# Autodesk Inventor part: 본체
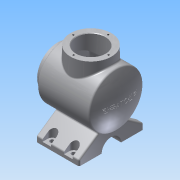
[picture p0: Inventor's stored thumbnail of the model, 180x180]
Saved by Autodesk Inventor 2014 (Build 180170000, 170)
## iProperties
Created: 2017-04
Part Number: 본체
Material: 알루미늄 6061
Document SubType Name: Modeling
Designer: SCD-A12
Density: 2.71 g/cm^3
Appearance: 알루미늄 - 평지
Mass: 1792.45 g
Surface Area: 1064.52 cm^2
Volume: 661.422 cm^3
Author: SCD-A12
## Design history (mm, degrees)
sketch "스케치1"
  geometry: L1 (12, 50)-(108.336, 50); L2 (0, 0)-(120, 0); L3 (0, 38)-(12, 38); L4 (12, 38)-(12, 50); L5 (0, 38)-(0, 0); L6 (0, 0)-(0, 27); L7 (0, 27)-(22, 27); L8 (22, 27)-(22, 37); L9 (25, 40)-(99.903, 40); L10 (120, 0)-(110, 0); L11 (62, 65)-(62, 0); L12 (62, 65)-(24, 65); L13 (24, 65)-(24, 0); L14 (66, 0)-(28, 0); L15 (35, 65)-(35, 0); L16 (39, 0)-(66, 0); L17 (24, 0)-(62, 0); L18 (35, 65)-(62, 65); L19 (62, 65)-(62, 0); L20 (62, 0)-(35, 0); L21 (35, 0)-(35, 65); L22 (120, 0)-(110, 0); A1 r 113 centre (7, 0) between (120, 0) and (108.336, 50); A2 r 3 centre (25, 37) between (25, 40) and (22, 37); A3 r 103 centre (7, 0) between (110, 0) and (102.69, 38.11); A4 r 3 centre (99.903, 37) between (102.69, 38.11) and (99.903, 40); 2 further points
  constraints: 44 end point, 10 perpendicular, 9 point on circle, 5 collinear, 5 point on line, 4 centre point, 4 tangent, 2 parallel
  dimensions: "d93" = 3 radius of A4; "d97" = 108 horizontal distance of L2.end L1.start
revolve "회전1" stored, may be unused: angle "d15" = 90 deg
revolve "회전2" stored, may be unused: angle "d18" = 90 deg
revolve "회전3" stored, may be unused: angle "d19" = 90 deg
revolve "회전4" stored, may be unused: angle "d20" = 90 deg
node "작업 평면1"
sketch "스케치2"
  geometry: L1 (18, -82)-(60, -82); L2 (60, -82)-(60, -72); L3 (60, -72)-(21.584, -45.101); L4 (-60, -82)-(-60, -72); L5 (-60, -72)-(-21.584, -45.101); L6 (-18, -82)-(-60, -82); A1 r 18 centre (0, -82) between (18, -82) and (-18, -82); A2 r 50 centre (0, 0) between (-21.584, -45.101) and (21.584, -45.101); 1 further point
  constraints: 12 end point, 4 point on circle, 2 centre point, 1 coincident, 1 perpendicular
  dimensions: "d85" = 55 deg angle of L2 L3; "d86" = 10 distance of L1.end L2.end; "d87" = 10 distance of L4.start L4.end; "d88" = 55 deg angle of L4 L5; "d89" = 42 distance of L6.start L4.start
extrude "돌출1" join sketch "스케치2" distance "d28" = 80; taper "d29" = 0 deg
node "작업 평면3"
sketch "스케치5"
  geometry: L1 (12, 110)-(12, 120); L2 (12, 120)-(28, 120); L3 (28, 120)-(28, 110); L4 (20, 110)-(20, 10); L5 (20, 10)-(20, 9); L6 (20, 9)-(20, 0); A1 r 8 centre (20, 110) between (12, 110) and (28, 110); 1 further point
  constraints: 12 end point, 2 collinear, 2 point on circle, 2 tangent, 1 centre point, 1 parallel, 1 perpendicular, 1 vertical
  dimensions: "d39" = 10 distance of L1.start L1.end; "d82" = 100 distance of L4.start L4.end; "d83" = 1 distance of L4.end L5.end; "d84" = 9 distance of L5.end L6.end
extrude "돌출2" cut sketch "스케치5" distance "d40" = 40; taper "d41" = 0 deg
hole "구멍1" sketch "스케치5" diameter "d42" = 8; stored, may be unused: countersink angle "d46" = 90 deg, drill point angle "d48" = 118 deg; dims "d43" = 6, "d44" = 4, "d45" = 2, "d47" = 8
sketch "스케치6" dims "d52" = 65
  geometry: L1 (0, 0)-(32.499, 0.269); C1 r 38 at (0, 0) reference; 2 further points
  constraints: 2 coincident, 2 end point, 6 other
hole "구멍2" sketch "스케치6" at (32.499, 0.269) diameter "d53" = 3.2; stored, may be unused: countersink angle "d57" = 90 deg, drill point angle "d59" = 118 deg; dims "d54" = 8, "d55" = 4, "d56" = 2, "d58" = 10
sketch "스케치7" dims "d63" = 65
  geometry: L1 (0, 0)-(32.5, 0); C1 r 38 at (0, 0) reference
  constraints: 2 end point, 1 coincident, 1 horizontal, 1 horizontal alignment, 2 other
hole "구멍3" sketch "스케치7" at (32.5, 0) diameter "d64" = 3.2; stored, may be unused: countersink angle "d68" = 90 deg, drill point angle "d70" = 118 deg; dims "d65" = 8, "d66" = 4, "d67" = 2, "d69" = 10
fillet "모깎기1" dims "d74" = 3
fillet "모깎기2" dims "d75" = 3
chamfer "모따기1" distance "d76" = 1; stored, may be unused: second distance "d77" = 2, angle "d78" = 45 deg
node "작업 평면4"
sketch "스케치8"
  geometry: 2 further points
  constraints: 1 coincident, 1 other
feature "엠보싱1" sketch "스케치8" dims "d80" = 0.5, "d81" = 0, "d93" = 3, "d97" = 108
node "솔리드1"
pattern_linear "직사각형 패턴1"
mirror "대칭1"
pattern_circular "원형 패턴1" dims angle "d61" = 360 deg
pattern_circular "원형 패턴3" dims angle "d95" = 360 deg
other parameters: "d21" = -8, "d35" = -6, "d79" = 160.5
